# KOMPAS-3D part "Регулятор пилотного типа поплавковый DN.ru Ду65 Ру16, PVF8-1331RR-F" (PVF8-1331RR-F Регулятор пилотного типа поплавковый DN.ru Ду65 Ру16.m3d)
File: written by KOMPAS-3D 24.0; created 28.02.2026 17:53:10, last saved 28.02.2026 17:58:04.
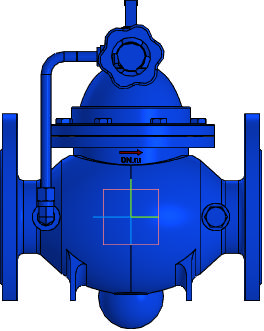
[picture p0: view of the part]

Document properties: Автор: R2D2; Полное имя файла: E:\Работа\Зайцев\PVF8-1331RR-F Регулятор пилотного типа поплавковый DN.ru Ду15-300\DN65\PVF8-1331RR-F Регулятор пилотного типа поплавковый DN.ru Ду65 Ру16.m3d

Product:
- Part/product: Регулятор пилотного типа поплавковый DN.ru Ду65 Ру16  | designation PVF8-1331RR-F
    Масса: 10
    Раздел спецификации: Прочие изделия
    Примечание: D230-10612
    additional columns: D230-10612

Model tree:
1. Операция без истории:2

Expressions: PVF8-1331RR-F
